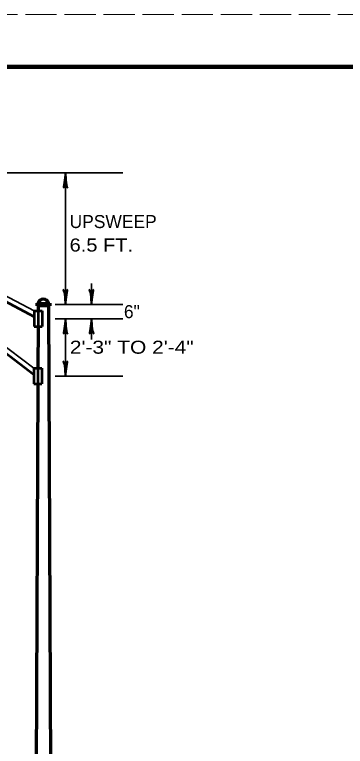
# Model space of a CAD drawing. Extents: x -1 to 679, y 1 to 441.
# Drawn here: x 297.3 to 360.8, y 300.5 to 440.9 of the extents above; entities that cross this region are included whole.
import ezdxf

# ---------------------------------------------------------------- set-up
doc = ezdxf.new("R2010")
doc.units = 0
doc.linetypes.add('LONG_DASHED', pattern=[7.5, 6, -1.5])
doc.layers.add('1', color=7, linetype='Continuous', lineweight=13)
doc.layers.add('61', color=7, linetype='Continuous', lineweight=35)

msp = doc.modelspace()

# ---------------------------------------------------------------- linework, layer by layer
at = {"layer": '1', "lineweight": 35}
for p, q in [((244.458, 410.517), (318.085, 410.517)), ((307.085, 385.267), (307.085, 410.517)), ((301.037, 373.017), (262.702, 401.904)), ((301.081, 384.017), (265.763, 402.796)), ((312.085, 385.267), (312.085, 389.267)), ((305.085, 385.267), (318.085, 385.267)), ((305.085, 382.517), (318.085, 382.517)), ((307.085, 371.517), (307.085, 382.517)), ((312.085, 378.517), (312.085, 382.517)), ((305.085, 371.517), (318.085, 371.517))]:
    msp.add_line(p, q, dxfattribs=at)
at = {"layer": '1', "lineweight": 53}
for p, q in [((301.081, 382.884), (265.294, 401.913)), ((301.037, 371.765), (262.1, 401.106)), ((301.585, 385.517), (304.085, 385.517)), ((301.585, 385.017), (304.085, 385.017)), ((301.081, 384.017), (302.581, 384.017)), ((301.081, 384.017), (301.081, 381.017)), ((301.831, 384.017), (301.819, 381.017)), ((302.581, 384.017), (302.581, 381.017)), ((301.081, 381.017), (302.581, 381.017)), ((301.037, 373.017), (302.537, 373.017)), ((301.037, 373.017), (301.037, 370.017)), ((301.787, 373.017), (301.775, 370.017)), ((302.537, 373.017), (302.537, 370.017)), ((301.037, 370.017), (302.537, 370.017))]:
    msp.add_line(p, q, dxfattribs=at)
at = {"layer": '1', "lineweight": 70}
for p, q in [((301.585, 385.517), (301.585, 385.017)), ((301.835, 385.017), (301.831, 384.017)), ((303.835, 385.017), (304.335, 261.017)), ((304.085, 385.517), (304.085, 385.017)), ((301.819, 381.017), (301.787, 373.017)), ((301.775, 370.017), (301.335, 261.017))]:
    msp.add_line(p, q, dxfattribs=at)
msp.add_arc((302.835, 385.271), 1.028, 13.87704, 166.12296, dxfattribs=at)
at = {"layer": '1', "lineweight": 40}
for centre, major_axis, ratio, start_param, end_param in [((306.874, 409.397), (0.176, 1.756), 0.07063, 3.1407148, 5.41811), ((306.874, 409.397), (0.176, 1.756), 0.07063, 3.1407148, 5.41811), ((307.362, 409.426), (-0.156, 1.786), 0.122415, 0.8963533, 3.1415927), ((307.362, 409.426), (-0.156, 1.786), 0.122415, 0.8963533, 3.1415927), ((306.809, 386.358), (0.156, -1.786), 0.122415, 0.8963533, 3.1415927), ((306.809, 386.358), (0.156, -1.786), 0.122415, 0.8963533, 3.1415927), ((307.297, 386.388), (-0.176, -1.756), 0.07063, 3.1407148, 5.41811), ((307.297, 386.388), (-0.176, -1.756), 0.07063, 3.1407148, 5.41811), ((311.809, 386.358), (0.156, -1.786), 0.122415, 0.8963533, 3.1415927), ((311.809, 386.358), (0.156, -1.786), 0.122415, 0.8963533, 3.1415927), ((312.297, 386.388), (-0.176, -1.756), 0.07063, 3.1407148, 5.41811), ((312.297, 386.388), (-0.176, -1.756), 0.07063, 3.1407148, 5.41811), ((306.874, 381.397), (0.176, 1.756), 0.07063, 3.1407148, 5.41811), ((306.874, 381.397), (0.176, 1.756), 0.07063, 3.1407148, 5.41811), ((307.362, 381.426), (-0.156, 1.786), 0.122415, 0.8963533, 3.1415927), ((307.362, 381.426), (-0.156, 1.786), 0.122415, 0.8963533, 3.1415927), ((311.874, 381.397), (0.176, 1.756), 0.07063, 3.1407148, 5.41811), ((311.874, 381.397), (0.176, 1.756), 0.07063, 3.1407148, 5.41811), ((312.362, 381.426), (-0.156, 1.786), 0.122415, 0.8963533, 3.1415927), ((312.362, 381.426), (-0.156, 1.786), 0.122415, 0.8963533, 3.1415927), ((306.809, 372.608), (0.156, -1.786), 0.122415, 0.8963533, 3.1415927), ((306.809, 372.608), (0.156, -1.786), 0.122415, 0.8963533, 3.1415927), ((307.297, 372.638), (-0.176, -1.756), 0.07063, 3.1407148, 5.41811), ((307.297, 372.638), (-0.176, -1.756), 0.07063, 3.1407148, 5.41811)]:
    msp.add_ellipse(centre, major_axis=major_axis, ratio=ratio, start_param=start_param, end_param=end_param, dxfattribs=at)
at = {"layer": '61', "linetype": 'LONG_DASHED', "lineweight": 13}
msp.add_line((-0.608, 440.866), (679.412, 440.866), dxfattribs=at)
at = {"layer": '61', "lineweight": 158}
msp.add_lwpolyline([(668.432, 430.866), (29.392, 430.866), (29.392, 10.846)], dxfattribs=at)

# ---------------------------------------------------------------- texts
at = {"layer": '1'}
for s, p in [('UPSWEEP', (307.877, 399.922)), ('6"', (318.304, 382.641))]:
    msp.add_text(s, height=2.5, dxfattribs=at).set_placement(p)
for s, width, p in [('6.5 FT.', 1.15, (307.877, 395.422)), ('2\'-3" TO 2\'-4"', 1.2, (307.929, 375.819))]:
    msp.add_text(s, height=2.5, dxfattribs=dict(at, width=width)).set_placement(p)

doc.saveas('drawing.dxf')
